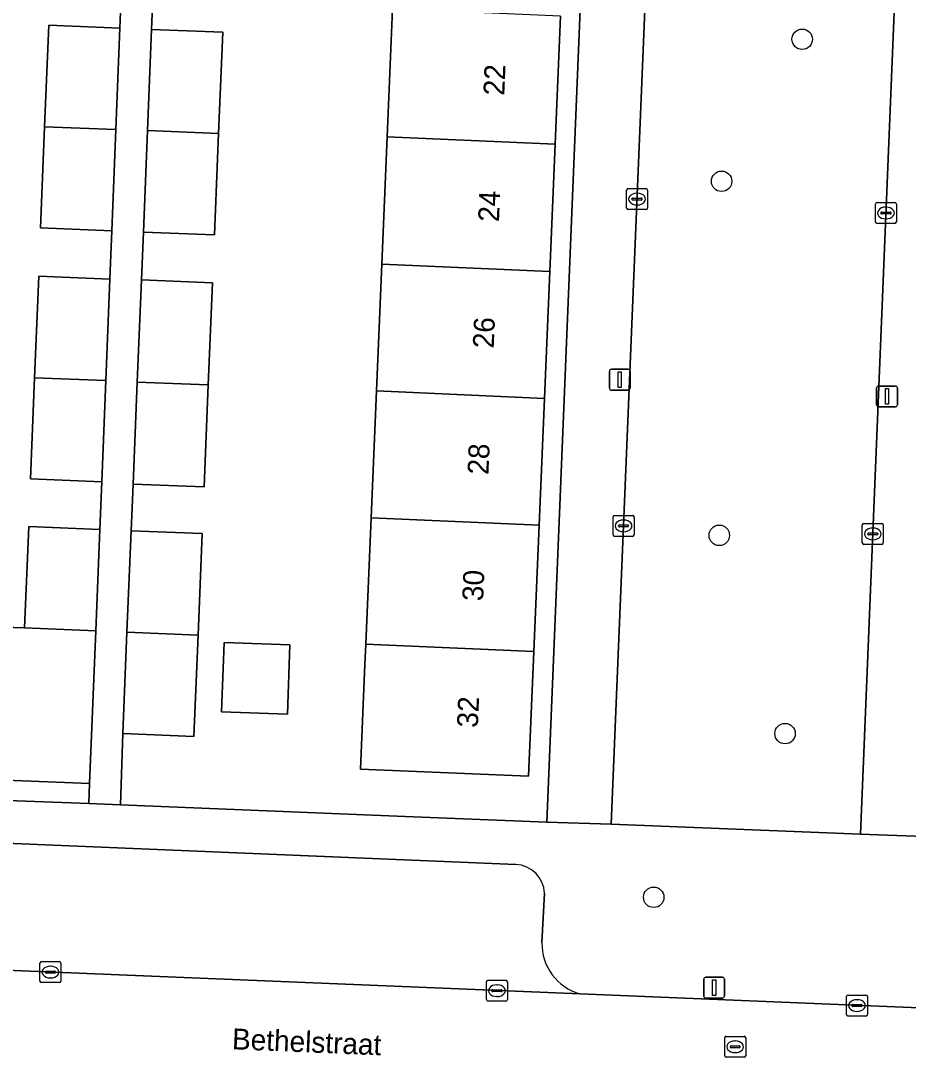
# Model space of a CAD drawing. Extents: x 161354 to 162026, y 386504 to 387460.
# Drawn here: x 161544.32 to 161586.73, y 387127.19 to 387176.73 of the extents above; entities that cross this region are included whole.
import ezdxf

# ---------------------------------------------------------------- set-up
doc = ezdxf.new("R2010")
doc.units = 0
for name, color, linetype in [('IMGEO_Boom', 7, 'Continuous'), ('IMGEO_Erf', 7, 'Continuous'), ('IMGEO_Groenvoorziening', 7, 'Continuous'), ('IMGEO_Kolk', 7, 'Continuous'), ('IMGEO_Lichtmast', 7, 'Continuous'), ('IMGEO_Muur', 7, 'Continuous'), ('IMGEO_Openbare_ruimte_label', 7, 'Continuous'), ('IMGEO_Pand', 7, 'Continuous'), ('IMGEO_Pand_nummerreeks', 7, 'Continuous'), ('IMGEO_Parkeervlak_open', 7, 'Continuous'), ('IMGEO_Rijbaan_lokaal_open', 7, 'Continuous'), ('IMGEO_Rioolput', 7, 'Continuous'), ('IMGEO_Voetpad_open', 7, 'Continuous')]:
    doc.layers.add(name, color=color, linetype=linetype)

msp = doc.modelspace()

# ---------------------------------------------------------------- linework, layer by layer
at = {"layer": 'IMGEO_Boom'}
for centre in [(161581.659, 387175.844), (161577.808, 387169.056), (161577.697, 387152.133), (161580.839, 387142.656), (161574.563, 387134.832)]:
    msp.add_circle(centre, 0.489, dxfattribs=at)
at = {"layer": 'IMGEO_Erf'}
for points in [[(161550.666, 387178.604), (161550.572, 387176.315), (161553.969, 387176.176), (161553.771, 387171.337), (161553.572, 387166.491), (161550.175, 387166.63), (161550.081, 387164.344), (161553.478, 387164.204), (161553.278, 387159.322), (161553.078, 387154.446), (161549.681, 387154.585), (161549.589, 387152.356), (161552.986, 387152.217), (161552.787, 387147.36), (161552.588, 387142.514), (161549.191, 387142.654), (161549.079, 387139.248), (161562.692, 387138.695), (161569.449, 387138.419), (161571.53, 387188.93)], [(161525.935, 387140.19), (161534.857, 387139.828), (161544.129, 387139.45), (161547.569, 387139.31), (161547.607, 387140.268), (161543.191, 387140.444), (161543.482, 387147.745), (161544.502, 387147.704), (161544.695, 387152.551), (161548.092, 387152.415), (161548.183, 387154.696), (161544.786, 387154.832), (161544.979, 387159.669), (161545.173, 387164.516), (161548.57, 387164.38), (161548.662, 387166.69), (161545.265, 387166.826), (161545.458, 387171.666), (161545.652, 387176.512), (161549.049, 387176.376), (161549.142, 387178.689)], [(161570.104, 387176.948), (161569.848, 387170.83), (161569.593, 387164.748), (161569.34, 387158.678), (161569.086, 387152.622), (161568.834, 387146.574), (161568.585, 387140.627), (161560.557, 387140.963), (161560.766, 387145.959), (161560.807, 387146.928), (161561.059, 387152.977), (161561.313, 387159.032), (161561.566, 387165.102), (161561.821, 387171.184), (161562.076, 387177.302)]]:
    msp.add_lwpolyline(points, dxfattribs=at)
msp.add_lwpolyline([(161557.062, 387143.587), (161553.917, 387143.694), (161554.03, 387147.004), (161557.174, 387146.897)], close=True, dxfattribs=at)
at = {"layer": 'IMGEO_Groenvoorziening'}
msp.add_lwpolyline([(161586.166, 387179.869), (161574.269, 387180.36), (161572.538, 387138.324), (161584.444, 387137.853)], close=True, dxfattribs=at)
at = {"layer": 'IMGEO_Kolk'}
for p, q in [((161573.266, 387167.778), (161573.266, 387168.63)), ((161573.341, 387168.704), (161574.193, 387168.704)), ((161573.754, 387168.484), (161573.779, 387168.484)), ((161574.267, 387168.63), (161574.267, 387167.778)), ((161573.525, 387168.198), (161573.525, 387168.21)), ((161573.963, 387168.161), (161573.565, 387168.161)), ((161573.568, 387168.247), (161573.966, 387168.247)), ((161573.777, 387167.924), (161573.752, 387167.924)), ((161574.009, 387168.21), (161574.009, 387168.198)), ((161585.161, 387167.115), (161585.161, 387167.967)), ((161585.236, 387168.041), (161586.088, 387168.041)), ((161586.162, 387167.967), (161586.162, 387167.115)), ((161574.193, 387167.704), (161573.341, 387167.704)), ((161585.42, 387167.535), (161585.42, 387167.547)), ((161585.858, 387167.498), (161585.46, 387167.498)), ((161585.463, 387167.584), (161585.861, 387167.584)), ((161585.649, 387167.821), (161585.674, 387167.821)), ((161585.904, 387167.547), (161585.904, 387167.535)), ((161586.088, 387167.041), (161585.236, 387167.041)), ((161585.672, 387167.261), (161585.647, 387167.261)), ((161572.698, 387153.085), (161573.55, 387153.085)), ((161572.623, 387152.159), (161572.623, 387153.011)), ((161572.882, 387152.579), (161572.882, 387152.591)), ((161573.32, 387152.542), (161572.922, 387152.542)), ((161572.925, 387152.628), (161573.323, 387152.628)), ((161573.111, 387152.865), (161573.136, 387152.865)), ((161573.366, 387152.591), (161573.366, 387152.579)), ((161573.624, 387153.011), (161573.624, 387152.159)), ((161584.532, 387151.776), (161584.532, 387152.628)), ((161584.607, 387152.702), (161585.459, 387152.702)), ((161585.533, 387152.628), (161585.533, 387151.776)), ((161573.55, 387152.085), (161572.698, 387152.085)), ((161573.134, 387152.305), (161573.109, 387152.305)), ((161584.791, 387152.196), (161584.791, 387152.208)), ((161585.229, 387152.159), (161584.831, 387152.159)), ((161584.834, 387152.245), (161585.232, 387152.245)), ((161585.02, 387152.482), (161585.045, 387152.482)), ((161585.275, 387152.208), (161585.275, 387152.196)), ((161585.459, 387151.702), (161584.607, 387151.702)), ((161585.043, 387151.922), (161585.018, 387151.922)), ((161545.307, 387131.756), (161546.159, 387131.756)), ((161545.232, 387130.83), (161545.232, 387131.682)), ((161545.491, 387131.25), (161545.491, 387131.262)), ((161545.534, 387131.299), (161545.932, 387131.299)), ((161545.72, 387131.536), (161545.745, 387131.536)), ((161545.975, 387131.262), (161545.975, 387131.25)), ((161546.233, 387131.682), (161546.233, 387130.83)), ((161546.159, 387130.756), (161545.307, 387130.756)), ((161545.929, 387131.213), (161545.531, 387131.213)), ((161545.743, 387130.976), (161545.718, 387130.976)), ((161566.572, 387129.942), (161566.572, 387130.794)), ((161566.647, 387130.868), (161567.499, 387130.868)), ((161567.573, 387130.794), (161567.573, 387129.942)), ((161566.831, 387130.362), (161566.831, 387130.374)), ((161567.269, 387130.325), (161566.871, 387130.325)), ((161566.874, 387130.411), (161567.272, 387130.411)), ((161567.06, 387130.648), (161567.085, 387130.648)), ((161567.315, 387130.374), (161567.315, 387130.362)), ((161567.499, 387129.868), (161566.647, 387129.868)), ((161567.083, 387130.088), (161567.058, 387130.088)), ((161583.777, 387129.232), (161583.777, 387130.084)), ((161583.852, 387130.158), (161584.704, 387130.158)), ((161584.265, 387129.938), (161584.29, 387129.938)), ((161584.778, 387130.084), (161584.778, 387129.232)), ((161584.036, 387129.652), (161584.036, 387129.664)), ((161584.474, 387129.615), (161584.076, 387129.615)), ((161584.079, 387129.701), (161584.477, 387129.701)), ((161584.288, 387129.378), (161584.263, 387129.378)), ((161584.52, 387129.664), (161584.52, 387129.652)), ((161584.704, 387129.158), (161583.852, 387129.158))]:
    msp.add_line(p, q, dxfattribs=at)
for points in [[(161573.266, 387167.778), (161573.266, 387168.63)], [(161573.341, 387168.704), (161574.193, 387168.704)], [(161574.267, 387168.63), (161574.267, 387167.778)], [(161585.161, 387167.115), (161585.161, 387167.967)], [(161585.236, 387168.041), (161586.088, 387168.041)], [(161586.162, 387167.967), (161586.162, 387167.115)], [(161574.193, 387167.704), (161573.341, 387167.704)], [(161586.088, 387167.041), (161585.236, 387167.041)], [(161572.698, 387153.085), (161573.55, 387153.085)], [(161572.623, 387152.159), (161572.623, 387153.011)], [(161573.624, 387153.011), (161573.624, 387152.159)], [(161584.532, 387151.776), (161584.532, 387152.628)], [(161584.607, 387152.702), (161585.459, 387152.702)], [(161585.533, 387152.628), (161585.533, 387151.776)], [(161573.55, 387152.085), (161572.698, 387152.085)], [(161585.459, 387151.702), (161584.607, 387151.702)], [(161545.307, 387131.756), (161546.159, 387131.756)], [(161545.232, 387130.83), (161545.232, 387131.682)], [(161546.233, 387131.682), (161546.233, 387130.83)], [(161546.159, 387130.756), (161545.307, 387130.756)], [(161566.572, 387129.942), (161566.572, 387130.794)], [(161566.647, 387130.868), (161567.499, 387130.868)], [(161567.573, 387130.794), (161567.573, 387129.942)], [(161567.499, 387129.868), (161566.647, 387129.868)], [(161583.777, 387129.232), (161583.777, 387130.084)], [(161583.852, 387130.158), (161584.704, 387130.158)], [(161584.778, 387130.084), (161584.778, 387129.232)], [(161584.704, 387129.158), (161583.852, 387129.158)]]:
    msp.add_lwpolyline(points, dxfattribs=at)
for centre, radius, start, end in [((161573.343, 387168.628), 0.0765, 91.552, 178.448), ((161573.343, 387168.628), 0.0765, 91.552, 178.448), ((161574.191, 387168.628), 0.0765, 1.552, 88.448), ((161574.191, 387168.628), 0.0765, 1.552, 88.448), ((161573.565, 387168.207), 0.0403, 85.8775, 175.7526), ((161573.562, 387168.197), 0.0366, 178.938, 274.7102), ((161573.966, 387168.204), 0.043, 264.8664, 352.4533), ((161573.97, 387168.209), 0.0386, 1.7309, 96.639), ((161585.238, 387167.965), 0.0765, 91.552, 178.448), ((161585.238, 387167.965), 0.0765, 91.552, 178.448), ((161586.086, 387167.965), 0.0765, 1.552, 88.448), ((161586.086, 387167.965), 0.0765, 1.552, 88.448), ((161573.343, 387167.78), 0.0765, 181.552, 268.448), ((161573.343, 387167.78), 0.0765, 181.552, 268.448), ((161574.191, 387167.78), 0.0765, 271.552, 358.448), ((161574.191, 387167.78), 0.0765, 271.552, 358.448), ((161585.46, 387167.544), 0.0403, 85.8775, 175.7526), ((161585.457, 387167.534), 0.0366, 178.938, 274.7102), ((161585.861, 387167.541), 0.043, 264.8664, 352.4533), ((161585.865, 387167.546), 0.0386, 1.7309, 96.639), ((161585.238, 387167.117), 0.0765, 181.552, 268.448), ((161585.238, 387167.117), 0.0765, 181.552, 268.448), ((161586.086, 387167.117), 0.0765, 271.552, 358.448), ((161586.086, 387167.117), 0.0765, 271.552, 358.448), ((161572.7, 387153.009), 0.0765, 91.552, 178.448), ((161572.7, 387153.009), 0.0765, 91.552, 178.448), ((161573.548, 387153.009), 0.0765, 1.552, 88.448), ((161573.548, 387153.009), 0.0765, 1.552, 88.448), ((161572.922, 387152.588), 0.0403, 85.8775, 175.7526), ((161572.919, 387152.578), 0.0366, 178.938, 274.7102), ((161573.323, 387152.585), 0.043, 264.8664, 352.4533), ((161573.327, 387152.59), 0.0386, 1.7309, 96.639), ((161584.609, 387152.626), 0.0765, 91.552, 178.448), ((161584.609, 387152.626), 0.0765, 91.552, 178.448), ((161585.457, 387152.626), 0.0765, 1.552, 88.448), ((161585.457, 387152.626), 0.0765, 1.552, 88.448), ((161572.7, 387152.161), 0.0765, 181.552, 268.448), ((161572.7, 387152.161), 0.0765, 181.552, 268.448), ((161573.548, 387152.161), 0.0765, 271.552, 358.448), ((161573.548, 387152.161), 0.0765, 271.552, 358.448), ((161584.831, 387152.205), 0.0403, 85.8775, 175.7526), ((161584.828, 387152.195), 0.0366, 178.938, 274.7102), ((161585.232, 387152.202), 0.043, 264.8664, 352.4533), ((161585.236, 387152.207), 0.0386, 1.7309, 96.639), ((161584.609, 387151.778), 0.0765, 181.552, 268.448), ((161584.609, 387151.778), 0.0765, 181.552, 268.448), ((161585.457, 387151.778), 0.0765, 271.552, 358.448), ((161585.457, 387151.778), 0.0765, 271.552, 358.448), ((161545.309, 387131.68), 0.0765, 91.552, 178.448), ((161545.309, 387131.68), 0.0765, 91.552, 178.448), ((161546.157, 387131.68), 0.0765, 1.552, 88.448), ((161546.157, 387131.68), 0.0765, 1.552, 88.448), ((161545.531, 387131.259), 0.0403, 85.8775, 175.7526), ((161545.528, 387131.249), 0.0366, 178.938, 274.7102), ((161545.932, 387131.256), 0.043, 264.8664, 352.4533), ((161545.936, 387131.261), 0.0386, 1.7309, 96.639), ((161545.309, 387130.832), 0.0765, 181.552, 268.448), ((161545.309, 387130.832), 0.0765, 181.552, 268.448), ((161546.157, 387130.832), 0.0765, 271.552, 358.448), ((161546.157, 387130.832), 0.0765, 271.552, 358.448), ((161566.649, 387130.792), 0.0765, 91.552, 178.448), ((161566.649, 387130.792), 0.0765, 91.552, 178.448), ((161567.497, 387130.792), 0.0765, 1.552, 88.448), ((161567.497, 387130.792), 0.0765, 1.552, 88.448), ((161566.871, 387130.371), 0.0403, 85.8775, 175.7526), ((161566.868, 387130.361), 0.0366, 178.938, 274.7102), ((161567.272, 387130.368), 0.043, 264.8664, 352.4533), ((161567.276, 387130.373), 0.0386, 1.7309, 96.639), ((161566.649, 387129.944), 0.0765, 181.552, 268.448), ((161566.649, 387129.944), 0.0765, 181.552, 268.448), ((161567.497, 387129.944), 0.0765, 271.552, 358.448), ((161567.497, 387129.944), 0.0765, 271.552, 358.448), ((161583.854, 387130.082), 0.0765, 91.552, 178.448), ((161583.854, 387130.082), 0.0765, 91.552, 178.448), ((161584.702, 387130.082), 0.0765, 1.552, 88.448), ((161584.702, 387130.082), 0.0765, 1.552, 88.448), ((161584.076, 387129.661), 0.0403, 85.8775, 175.7526), ((161584.073, 387129.651), 0.0366, 178.938, 274.7102), ((161584.477, 387129.658), 0.043, 264.8664, 352.4533), ((161584.481, 387129.663), 0.0386, 1.7309, 96.639), ((161583.854, 387129.234), 0.0765, 181.552, 268.448), ((161583.854, 387129.234), 0.0765, 181.552, 268.448), ((161584.702, 387129.234), 0.0765, 271.552, 358.448), ((161584.702, 387129.234), 0.0765, 271.552, 358.448)]:
    msp.add_arc(centre, radius, start, end, dxfattribs=at)
for centre, major_axis, ratio, start_param, end_param in [((161573.753, 387168.204), (-0.387, 0.002), 0.722429, 4.712389, 7.853982), ((161573.778, 387168.204), (-0.39, 0.002), 0.717154, 1.570796, 4.712389), ((161585.648, 387167.541), (-0.387, 0.002), 0.722429, 4.712389, 7.853982), ((161585.673, 387167.541), (-0.39, 0.002), 0.717154, 1.570796, 4.712389), ((161573.11, 387152.585), (-0.387, 0.002), 0.722429, 4.712389, 7.853982), ((161573.135, 387152.585), (-0.39, 0.002), 0.717154, 1.570796, 4.712389), ((161585.019, 387152.202), (-0.387, 0.002), 0.722429, 4.712389, 7.853982), ((161585.044, 387152.202), (-0.39, 0.002), 0.717154, 1.570796, 4.712389), ((161545.719, 387131.256), (-0.387, 0.002), 0.722429, 4.712389, 7.853982), ((161545.744, 387131.256), (-0.39, 0.002), 0.717154, 1.570796, 4.712389), ((161567.059, 387130.368), (-0.387, 0.002), 0.722429, 4.712389, 7.853982), ((161567.084, 387130.368), (-0.39, 0.002), 0.717154, 1.570796, 4.712389), ((161584.264, 387129.658), (-0.387, 0.002), 0.722429, 4.712389, 7.853982), ((161584.289, 387129.658), (-0.39, 0.002), 0.717154, 1.570796, 4.712389)]:
    msp.add_ellipse(centre, major_axis=major_axis, ratio=ratio, start_param=start_param, end_param=end_param, dxfattribs=at)
at = {"layer": 'IMGEO_Lichtmast'}
for p, q in [((161572.545, 387160.069), (161573.335, 387160.069)), ((161573.335, 387160.069), (161572.545, 387160.069)), ((161572.445, 387159.169), (161572.445, 387159.969)), ((161572.445, 387159.969), (161572.445, 387159.169)), ((161573.435, 387159.969), (161573.435, 387159.169)), ((161573.435, 387159.169), (161573.435, 387159.969)), ((161573.335, 387159.069), (161572.545, 387159.069)), ((161572.545, 387159.069), (161573.335, 387159.069)), ((161585.217, 387158.37), (161585.217, 387159.17)), ((161585.217, 387159.17), (161585.217, 387158.37)), ((161585.317, 387159.27), (161586.107, 387159.27)), ((161586.107, 387159.27), (161585.317, 387159.27)), ((161586.207, 387159.17), (161586.207, 387158.37)), ((161586.207, 387158.37), (161586.207, 387159.17)), ((161586.107, 387158.27), (161585.317, 387158.27)), ((161585.317, 387158.27), (161586.107, 387158.27)), ((161576.956, 387130.114), (161576.956, 387130.914)), ((161576.956, 387130.914), (161576.956, 387130.114)), ((161577.056, 387131.014), (161577.846, 387131.014)), ((161577.846, 387131.014), (161577.056, 387131.014)), ((161577.946, 387130.914), (161577.946, 387130.114)), ((161577.946, 387130.114), (161577.946, 387130.914)), ((161577.846, 387130.014), (161577.056, 387130.014)), ((161577.056, 387130.014), (161577.846, 387130.014))]:
    msp.add_line(p, q, dxfattribs=at)
for points in [[(161572.865, 387159.944), (161573.015, 387159.944), (161573.015, 387159.194), (161572.865, 387159.194), (161572.865, 387159.944)], [(161585.637, 387159.145), (161585.787, 387159.145), (161585.787, 387158.395), (161585.637, 387158.395), (161585.637, 387159.145)], [(161577.376, 387130.889), (161577.526, 387130.889), (161577.526, 387130.139), (161577.376, 387130.139), (161577.376, 387130.889)]]:
    msp.add_lwpolyline(points, dxfattribs=at)
for centre, start, end in [((161572.545, 387159.969), 90, 180), ((161572.545, 387159.969), 90, 180), ((161573.335, 387159.969), 0, 90), ((161573.335, 387159.969), 360, 90), ((161572.545, 387159.169), 180, 270), ((161572.545, 387159.169), 180, 270), ((161573.335, 387159.169), 270, 0), ((161573.335, 387159.169), 270, 0), ((161585.317, 387159.17), 90, 180), ((161585.317, 387159.17), 90, 180), ((161586.107, 387159.17), 0, 90), ((161586.107, 387159.17), 360, 90), ((161585.317, 387158.37), 180, 270), ((161585.317, 387158.37), 180, 270), ((161586.107, 387158.37), 270, 0), ((161586.107, 387158.37), 270, 0), ((161577.056, 387130.914), 90, 180), ((161577.056, 387130.914), 90, 180), ((161577.846, 387130.914), 0, 90), ((161577.846, 387130.914), 360, 90), ((161577.056, 387130.114), 180, 270), ((161577.056, 387130.114), 180, 270), ((161577.846, 387130.114), 270, 0), ((161577.846, 387130.114), 270, 0)]:
    msp.add_arc(centre, 0.1, start, end, dxfattribs=at)
at = {"layer": 'IMGEO_Muur'}
msp.add_lwpolyline([(161562.692, 387138.695), (161548.933, 387139.254)], dxfattribs=at)
at = {"layer": 'IMGEO_Pand'}
for points in [[(161562.076, 387177.302), (161561.821, 387171.184), (161569.848, 387170.83), (161570.104, 387176.948)], [(161549.049, 387176.376), (161545.652, 387176.512), (161545.458, 387171.666), (161548.856, 387171.53)], [(161550.572, 387176.315), (161550.374, 387171.476), (161553.771, 387171.337), (161553.969, 387176.176)], [(161548.856, 387171.53), (161545.458, 387171.666), (161545.265, 387166.826), (161548.662, 387166.69)], [(161553.771, 387171.337), (161550.374, 387171.476), (161550.175, 387166.63), (161553.572, 387166.491)], [(161569.593, 387164.748), (161569.848, 387170.83), (161561.821, 387171.184), (161561.566, 387165.102)], [(161569.34, 387158.678), (161569.593, 387164.748), (161561.566, 387165.102), (161561.313, 387159.032)], [(161548.57, 387164.38), (161545.173, 387164.516), (161544.979, 387159.669), (161548.377, 387159.534)], [(161550.081, 387164.344), (161549.881, 387159.461), (161553.278, 387159.322), (161553.478, 387164.204)], [(161548.377, 387159.534), (161544.979, 387159.669), (161544.786, 387154.832), (161548.183, 387154.696)], [(161553.278, 387159.322), (161549.881, 387159.461), (161549.681, 387154.585), (161553.078, 387154.446)], [(161561.313, 387159.032), (161561.059, 387152.977), (161569.086, 387152.622), (161569.34, 387158.678)], [(161548.092, 387152.415), (161544.695, 387152.551), (161544.502, 387147.704), (161547.899, 387147.569)], [(161568.834, 387146.574), (161569.086, 387152.622), (161561.059, 387152.977), (161560.807, 387146.928)], [(161549.589, 387152.356), (161549.39, 387147.5), (161552.787, 387147.36), (161552.986, 387152.217)], [(161547.899, 387147.569), (161544.502, 387147.704), (161543.482, 387147.745), (161543.191, 387140.444), (161547.607, 387140.268)], [(161552.787, 387147.36), (161549.39, 387147.5), (161549.191, 387142.654), (161552.588, 387142.514)], [(161554.03, 387147.004), (161553.917, 387143.694), (161557.062, 387143.587), (161557.174, 387146.897)], [(161560.807, 387146.928), (161560.766, 387145.959), (161560.557, 387140.963), (161568.585, 387140.627), (161568.834, 387146.574)]]:
    msp.add_lwpolyline(points, close=True, dxfattribs=at)
at = {"layer": 'IMGEO_Parkeervlak_open'}
for points in [[(161567.968, 387136.396), (161530.248, 387137.98)], [(161569.221, 387132.666), (161569.34, 387135.026)], [(161526.596, 387132.052), (161571.042, 387130.218)]]:
    msp.add_lwpolyline(points, dxfattribs=at)
for centre, radius, start, end in [((161567.934, 387134.99), 1.406, 1.4678, 88.6158), ((161571.721, 387132.625), 2.501, 179.0528, 254.2363)]:
    msp.add_arc(centre, radius, start, end, dxfattribs=at)
at = {"layer": 'IMGEO_Rijbaan_lokaal_open'}
msp.add_lwpolyline([(161628.361, 387127.854), (161627.435, 387127.892), (161587.249, 387129.55), (161571.042, 387130.218), (161526.596, 387132.052), (161526.224, 387132.067)], dxfattribs=at)
at = {"layer": 'IMGEO_Rioolput'}
for p, q in [((161577.957, 387127.26), (161577.957, 387128.112)), ((161578.032, 387128.186), (161578.884, 387128.186)), ((161578.445, 387127.966), (161578.47, 387127.966)), ((161578.958, 387128.112), (161578.958, 387127.26)), ((161578.216, 387127.68), (161578.216, 387127.692)), ((161578.654, 387127.643), (161578.256, 387127.643)), ((161578.259, 387127.729), (161578.657, 387127.729)), ((161578.468, 387127.406), (161578.443, 387127.406)), ((161578.7, 387127.692), (161578.7, 387127.68)), ((161578.884, 387127.186), (161578.032, 387127.186))]:
    msp.add_line(p, q, dxfattribs=at)
for points in [[(161577.957, 387127.26), (161577.957, 387128.112)], [(161578.032, 387128.186), (161578.884, 387128.186)], [(161578.958, 387128.112), (161578.958, 387127.26)], [(161578.884, 387127.186), (161578.032, 387127.186)]]:
    msp.add_lwpolyline(points, dxfattribs=at)
for centre, radius, start, end in [((161578.034, 387128.11), 0.0765, 91.552, 178.448), ((161578.034, 387128.11), 0.0765, 91.552, 178.448), ((161578.882, 387128.11), 0.0765, 1.552, 88.448), ((161578.882, 387128.11), 0.0765, 1.552, 88.448), ((161578.256, 387127.689), 0.0403, 85.8775, 175.7526), ((161578.253, 387127.679), 0.0366, 178.938, 274.7102), ((161578.657, 387127.686), 0.043, 264.8664, 352.4533), ((161578.661, 387127.691), 0.0386, 1.7309, 96.639), ((161578.034, 387127.262), 0.0765, 181.552, 268.448), ((161578.034, 387127.262), 0.0765, 181.552, 268.448), ((161578.882, 387127.262), 0.0765, 271.552, 358.448), ((161578.882, 387127.262), 0.0765, 271.552, 358.448)]:
    msp.add_arc(centre, radius, start, end, dxfattribs=at)
for centre, major_axis, ratio, start_param, end_param in [((161578.444, 387127.686), (-0.387, 0.002), 0.722429, 4.712389, 7.853982), ((161578.469, 387127.686), (-0.39, 0.002), 0.717154, 1.570796, 4.712389)]:
    msp.add_ellipse(centre, major_axis=major_axis, ratio=ratio, start_param=start_param, end_param=end_param, dxfattribs=at)
at = {"layer": 'IMGEO_Voetpad_open'}
msp.add_lwpolyline([(161589.496, 387188.206), (161589.556, 387189.7), (161572.553, 387190.267), (161571.587, 387190.31), (161571.53, 387188.93), (161569.449, 387138.419), (161572.538, 387138.324), (161574.269, 387180.36), (161586.166, 387179.869), (161584.444, 387137.853), (161587.468, 387137.733)], close=True, dxfattribs=at)
for points in [[(161549.142, 387178.689), (161549.049, 387176.376), (161548.856, 387171.53), (161548.662, 387166.69), (161548.57, 387164.38), (161548.377, 387159.534), (161548.183, 387154.696), (161548.092, 387152.415), (161547.899, 387147.569), (161547.607, 387140.268), (161547.569, 387139.31), (161549.079, 387139.248), (161549.191, 387142.654), (161549.39, 387147.5), (161549.589, 387152.356), (161549.681, 387154.585), (161549.881, 387159.461), (161550.081, 387164.344), (161550.175, 387166.63), (161550.374, 387171.476), (161550.572, 387176.315), (161550.666, 387178.604)], [(161587.468, 387137.733), (161584.444, 387137.853), (161572.538, 387138.324), (161569.449, 387138.419), (161562.692, 387138.695), (161549.079, 387139.248), (161547.569, 387139.31), (161544.129, 387139.45), (161534.857, 387139.828), (161525.935, 387140.19)], [(161530.248, 387137.98), (161567.968, 387136.396)], [(161569.34, 387135.026), (161569.221, 387132.666)], [(161571.042, 387130.218), (161587.249, 387129.55)]]:
    msp.add_lwpolyline(points, dxfattribs=at)
for centre, radius, start, end in [((161567.934, 387134.99), 1.406, 1.4678, 88.6158), ((161571.721, 387132.625), 2.501, 179.0528, 254.2363)]:
    msp.add_arc(centre, radius, start, end, dxfattribs=at)

# ---------------------------------------------------------------- texts
at = {"layer": 'IMGEO_Openbare_ruimte_label'}
msp.add_text('Bethelstraat', height=1, rotation=357.6498, dxfattribs=at).set_placement((161554.398, 387127.57))
at = {"layer": 'IMGEO_Pand_nummerreeks'}
for s, p in [('22', (161567.422, 387173.138)), ('24', (161567.169, 387167.098)), ('26', (161566.917, 387161.056)), ('28', (161566.664, 387155.016)), ('30', (161566.411, 387148.974)), ('32', (161566.159, 387142.925))]:
    msp.add_text(s, height=1, rotation=87.606, dxfattribs=at).set_placement(p)

doc.saveas('drawing.dxf')
